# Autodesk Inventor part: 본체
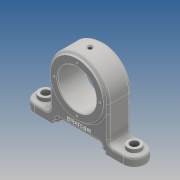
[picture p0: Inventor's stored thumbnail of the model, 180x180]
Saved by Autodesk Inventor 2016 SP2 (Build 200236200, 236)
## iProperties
Created: 2019-05
Part Number: 본체
Material: Generic
Document SubType Name: Modeling
Designer: EZ
Density: 1 g/cm^3
Appearance: Default
Author: EZ
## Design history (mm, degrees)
sketch "스케치1"
  geometry: L1 (-75, -15)-(75, -15); L2 (75, -15)-(75, 15); L3 (75, 15)-(-75, 15); L4 (-75, 15)-(-75, -15); L5 (-75, -15)-(75, 15); L6 (75, -15)-(-75, 15); 1 further point
  constraints: 12 end point, 2 midpoint, 2 parallel, 1 horizontal, 1 perpendicular
  dimensions: "d0" = 150 distance of L3.end L2.end; "d1" = 30 distance of L2.end L1.end
extrude "돌출1" new body sketch "스케치1" distance "d2" = 12; taper "d3" = 0 deg
sketch "스케치2"
  geometry: L1 (120.991, 60)-(-120.991, 60); L2 (-75, 0)-(75, 0) reference; L3 (-75, 12)-(75, 12) reference; L4 (-40, 60)-(-40, 12); L5 (40, 60)-(40, 12); A1 r 40 centre (0, 60) between (40, 60) and (-40, 60); 2 further points
  constraints: 6 end point, 3 point on line, 2 point on circle, 2 tangent, 1 centre point, 1 coincident, 1 horizontal, 1 midpoint, 1 perpendicular, 1 vertical, 1 vertical alignment
  dimensions: "d4" = 60 distance between parallel lines of L2 L1; "d5" = 80 diameter of A1
extrude "돌출2" join sketch "스케치2" stored distance "d6" = 30; taper "d7" = 0 deg
sketch "스케치3"
  geometry: L1 (-75, 0)-(75, 0) reference; L2 (75, 0)-(75, 12) reference; L3 (40, 12)-(75, 12) reference; L4 (40, 12)-(40, 60) reference; L5 (-40, 60)-(-40, 12) reference; L6 (-75, 12)-(-40, 12) reference; L7 (-75, 0)-(-75, 12) reference; C1 r 36 at (0, 60); A1 r 40 centre (0, 60) between (40, 60) and (-40, 60) reference; 1 further point
  constraints: 1 centre point, 1 coincident
  dimensions: "d8" = 72 diameter of C1
extrude "돌출3" join sketch "스케치3" stored distance "d9" = 36; taper "d10" = 0 deg
sketch "스케치4"
  geometry: L1 (0, 0)-(150, 0) reference; L2 (150, 0)-(150, 12) reference; L3 (115, 12)-(150, 12) reference; L4 (115, 12)-(115, 60) reference; L5 (35, 60)-(35, 12) reference; L6 (0, 12)-(35, 12) reference; L7 (0, 0)-(0, 12) reference; L8 (39, 0)-(39, 4); L9 (39, 4)-(45, 4); L10 (45, 4)-(45, 10); L11 (45, 10)-(105, 10); L12 (105, 10)-(105, 4); L13 (105, 4)-(111, 4); L14 (111, 4)-(111, 0); C1 r 36 at (75, 60) reference; A1 r 40 centre (75, 60) between (115, 60) and (35, 60) reference; 1 further point
  constraints: 14 end point, 6 perpendicular, 4 point on line
  dimensions: "d11" = 72 distance between parallel lines of L14 L8; "d12" = 36 distance from line of L8 point (75, 0); "d13" = 4 distance between parallel lines of L1 L9; "d14" = 10 distance between parallel lines of L1 L11; "d15" = 60 distance between parallel lines of L12 L10; "d16" = 30 distance from line of point (75, 0) L10
extrude "돌출4" cut sketch "스케치4" stored distance "d17" = 36; taper "d18" = 0 deg
fillet "모깎기1" dims "d19" = 15
sketch "스케치6"
  geometry: L1 (-36, 15)-(-60, 15) reference; L2 (-36, 15)-(-36, -15) reference; L3 (-60, -15)-(-36, -15) reference; L4 (36, -15)-(60, -15) reference; L5 (36, -15)-(36, 15) reference; L6 (60, 15)-(36, 15) reference; C1 r 9 at (-60, 0); C2 r 9 at (60, 0); A1 r 15 centre (-60, 0) between (-60, 15) and (-60, -15) reference; A2 r 15 centre (60, 0) between (60, -15) and (60, 15) reference; 1 further point
  constraints: 2 centre point, 2 coincident
  dimensions: "d20" = 18 diameter of C1; "d21" = 18 diameter of C2
extrude "돌출5" join sketch "스케치6" distance "d22" = 5; taper "d23" = 0 deg
hole "구멍1" diameter "d26" = 11; stored, may be unused: countersink angle "d30" = 90 deg, drill point angle "d32" = 118 deg; dims "d24" = 10, "d25" = 10, "d27" = 6, "d28" = 4, "d29" = 2, "d31" = 8
hole "구멍2" diameter "d35" = 11; stored, may be unused: countersink angle "d39" = 90 deg, drill point angle "d41" = 118 deg; dims "d33" = 10, "d34" = 10, "d36" = 6, "d37" = 4, "d38" = 2, "d40" = 8
sketch "스케치7"
  geometry: L1 (-18, 96)-(-18, 24) reference; L2 (18, 24)-(18, 96) reference; L3 (-18, 60)-(18, 60); L4 (-18, 86)-(18, 86); L5 (-18, 86)-(-18, 60); L6 (18, 86)-(18, 60); 1 further point
  constraints: 8 end point, 3 midpoint, 3 point on line, 1 horizontal, 1 perpendicular, 1 vertical
  dimensions: "d42" = 52 diameter of L4 L3
revolve "회전1" sketch "스케치7" stored, may be unused: angle "d43" = 90 deg
fillet "모깎기2" dims "d44" = 6
sketch "스케치8" dims "d45" = 62
  geometry: C1 r 26 at (0, 0) reference; C2 r 36 at (0, 0) reference; 3 further points
  constraints: 2 vertical alignment, 1 coincident, 2 other
hole "구멍3" sketch "스케치8" at (0, 31) diameter "d46" = 3.242; stored, may be unused: countersink angle "d50" = 90 deg, drill point angle "d52" = 118 deg; dims "d47" = 6, "d48" = 4, "d49" = 2, "d51" = 8
node "작업 평면1"
sketch "스케치9"
  geometry: 2 further points
  constraints: 1 coincident
hole "구멍4" sketch "스케치9" at (0, 0) diameter "d57" = 4.917; stored, may be unused: countersink angle "d61" = 90 deg, drill point angle "d63" = 118 deg; dims "d58" = 8, "d59" = 7, "d60" = 1, "d62" = 10
hole "구멍5" diameter "d66" = 2; stored, may be unused: countersink angle "d70" = 90 deg, drill point angle "d72" = 118 deg; dims "d64" = 10, "d65" = 10, "d67" = 8, "d68" = 7, "d69" = 1, "d71" = 10
sketch "스케치11"
  geometry: C1 r 1.621 at (-31, 0) reference; C2 r 1.621 at (0, -31) reference; C3 r 1.621 at (31, 0) reference; C4 r 1.621 at (0, 31) reference; C5 r 36 at (0, 0) reference; 3 further points
  constraints: 2 vertical alignment, 1 other
hole "구멍6" sketch "스케치11" at (0, 26) diameter "d73" = 3; stored, may be unused: countersink angle "d77" = 90 deg, drill point angle "d79" = 118 deg; dims "d74" = 8, "d75" = 7, "d76" = 1, "d78" = 10
chamfer "모따기1" distance "d80" = 1; stored, may be unused: second distance "d81" = 2, angle "d82" = 45 deg
fillet "모깎기3" dims "d83" = 3
fillet "모깎기4" dims "d84" = 3
fillet "모깎기5" dims "d85" = 3
sketch "스케치13"
  geometry: L1 (9, 10)-(63, 10) reference; L2 (82, 9)-(96, 9) reference; L3 (73, 47.671)-(73, 18) reference; L4 (-1, 18)-(-1, 47.671) reference; L5 (-24, 9)-(-10, 9) reference; L6 (-24, 0)-(-24, 9) reference; L7 (-24, 0)-(0, 0) reference; L8 (0, 0)-(0, 4) reference; L9 (0, 4)-(3, 4) reference; L10 (3, 7)-(3, 4) reference; L11 (63, 13)-(9, 13) reference; L12 (69, 4)-(69, 7) reference; L13 (69, 4)-(72, 4) reference; L14 (72, 4)-(72, 0) reference; L15 (72, 0)-(96, 0) reference; L16 (96, 9)-(96, 0) reference; A1 r 9 centre (82, 18) between (73, 18) and (82, 9) reference; A2 r 39 centre (36, 60) between (-1, 47.671) and (73, 47.671) reference; A3 r 9 centre (-10, 18) between (-10, 9) and (-1, 18) reference; A4 r 6 centre (9, 7) between (9, 13) and (3, 7) reference; A5 r 6 centre (63, 7) between (69, 7) and (63, 13) reference; 2 further points
  constraints: 1 vertical alignment, 1 other
  dimensions: "d86" = 7 distance from line of L1 point (36, 17)
feature "엠보싱1" sketch "스케치13" dims "d0" = 150, "d1" = 30, "d87" = 0.5, "d88" = 0
node "솔리드1"
pattern_circular "원형 패턴1" dims angle "d54" = 360 deg
mirror "대칭1"
node "투영된 루프1"
node "투영된 루프2"
node "투영된 루프5"
node "투영된 루프6"
node "투영된 루프7"
node "투영된 루프8"
node "투영된 루프9"
